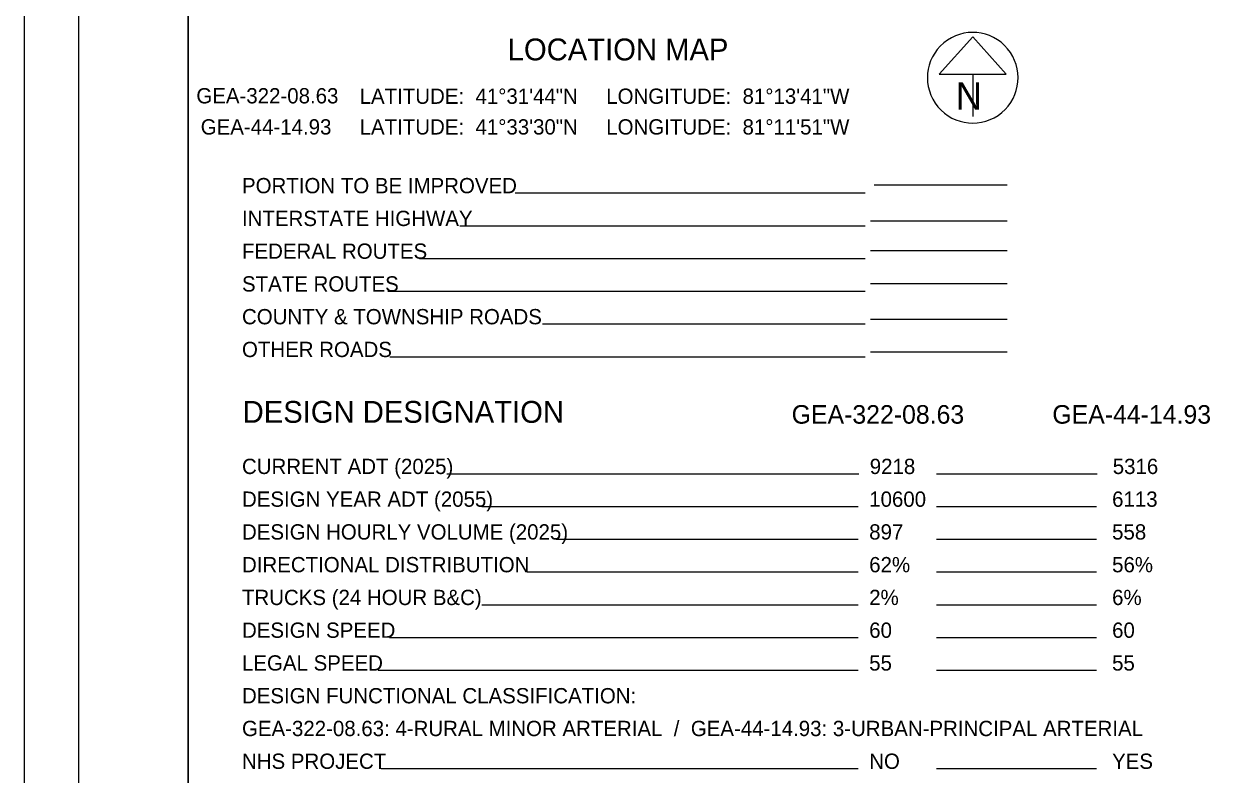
# Model space of a CAD drawing. Extents: x -6.1 to 38, y -7.7 to 22.
# Drawn here: x 0 to 11.09, y 7.05 to 13.93 of the extents above; entities that cross this region are included whole.
import ezdxf

# ---------------------------------------------------------------- set-up
doc = ezdxf.new("R2010")
doc.units = 0
for name, color, linetype in [('Default', 7, 'Continuous'), ('SH_Border', 7, 'Continuous'), ('SH_Cut_Line', 7, 'Continuous'), ('SH_Data', 7, 'Continuous'), ('SH_Text', 7, 'Continuous')]:
    doc.layers.add(name, color=color, linetype=linetype)

msp = doc.modelspace()

# ---------------------------------------------------------------- linework, layer by layer
at = {"layer": 'SH_Border'}
for points in [[(0.5, 21.5), (1.5, 21.5), (1.5, 0.5), (0.5, 0.5)], [(1.5, 21.5), (33.5, 21.5), (33.5, 0.5), (1.5, 0.5)]]:
    msp.add_lwpolyline(points, close=True, dxfattribs=at)
at = {"layer": 'SH_Cut_Line'}
msp.add_lwpolyline([(0, 0), (34, 0), (34, 22), (0, 22)], close=True, dxfattribs=at)
at = {"layer": 'SH_Data'}
for p, q in [((8.685, 13.809), (8.377, 13.468)), ((8.992, 13.468), (8.685, 13.809)), ((8.377, 13.468), (8.992, 13.468)), ((8.685, 13.468), (8.685, 13.081)), ((8.685, 13.435), (8.685, 13.435)), ((8.685, 13.435), (8.685, 13.435)), ((7.783, 12.455), (9, 12.455)), ((7.7, 12.377), (4.494, 12.377)), ((9, 12.121), (7.75, 12.121)), ((7.7, 12.077), (3.99, 12.077)), ((7.7, 11.777), (3.619, 11.777)), ((9, 11.849), (7.75, 11.849)), ((9, 11.549), (7.75, 11.549)), ((7.7, 11.477), (3.329, 11.477)), ((9, 11.222), (7.75, 11.222)), ((7.7, 11.177), (4.745, 11.177)), ((7.7, 10.877), (3.347, 10.877)), ((9, 10.922), (7.75, 10.922)), ((7.642, 9.806), (3.871, 9.806)), ((9.824, 9.806), (8.352, 9.806)), ((7.637, 9.506), (4.189, 9.506)), ((9.818, 9.506), (8.352, 9.506)), ((7.637, 9.206), (4.872, 9.206)), ((9.818, 9.206), (8.352, 9.206)), ((7.637, 8.906), (4.604, 8.906)), ((9.818, 8.906), (8.352, 8.906)), ((7.637, 8.606), (4.189, 8.606)), ((9.818, 8.606), (8.352, 8.606)), ((7.637, 8.306), (3.346, 8.306)), ((9.818, 8.306), (8.352, 8.306)), ((7.637, 8.006), (3.242, 8.006)), ((9.818, 8.006), (8.352, 8.006)), ((7.637, 7.106), (3.267, 7.106)), ((9.818, 7.106), (8.352, 7.106))]:
    msp.add_line(p, q, dxfattribs=at)
msp.add_arc((8.685, 13.435), 0.415, 129.7798, 129.7633, dxfattribs=at)

# ---------------------------------------------------------------- texts
at = {"layer": 'Default'}
for s, height, p in [('GEA-322-08.63', 0.14, (1.576, 13.2)), ('GEA-44-14.93', 0.14, (1.616, 12.915)), ('GEA-322-08.63', 0.17, (7.027, 10.267)), ('GEA-44-14.93', 0.17, (9.414, 10.267)), ('5316', 0.14, (9.967, 9.806)), ('6113', 0.14, (9.961, 9.506)), ('558', 0.14, (9.961, 9.206)), ('56%', 0.14, (9.961, 8.906)), ('6%', 0.14, (9.961, 8.606)), ('60', 0.14, (9.961, 8.306)), ('55', 0.14, (9.961, 8.006)), ('YES', 0.14, (9.961, 7.106))]:
    msp.add_text(s, height=height, dxfattribs=at).set_placement(p)
at = {"layer": 'SH_Data'}
for s, height, p in [('N', 0.25, (8.529, 13.144)), ('DESIGN DESIGNATION', 0.2, (2, 10.275))]:
    msp.add_text(s, height=height, dxfattribs=at).set_placement(p)
at = {"layer": 'SH_Text'}
for s, height, p in [('LOCATION MAP', 0.2, (4.427, 13.594)), ('LATITUDE:  41°31\'44"N     LONGITUDE:  81°13\'41"W', 0.14, (3.071, 13.196)), ('LATITUDE:  41°33\'30"N     LONGITUDE:  81°11\'51"W', 0.14, (3.071, 12.915)), ('PORTION TO BE IMPROVED', 0.14, (1.994, 12.377)), ('INTERSTATE HIGHWAY', 0.14, (1.994, 12.077)), ('FEDERAL ROUTES', 0.14, (1.994, 11.777)), ('STATE ROUTES', 0.14, (1.994, 11.477)), ('COUNTY & TOWNSHIP ROADS', 0.14, (1.994, 11.177)), ('OTHER ROADS', 0.14, (1.994, 10.877)), ('CURRENT ADT (2025)', 0.14, (1.994, 9.806)), ('9218', 0.14, (7.742, 9.806)), ('DESIGN YEAR ADT (2055)', 0.14, (1.994, 9.506)), ('10600', 0.14, (7.737, 9.506)), ('DESIGN HOURLY VOLUME (2025)', 0.14, (1.994, 9.206)), ('897', 0.14, (7.737, 9.206)), ('DIRECTIONAL DISTRIBUTION', 0.14, (1.994, 8.906)), ('62%', 0.14, (7.737, 8.906)), ('TRUCKS (24 HOUR B&C)', 0.14, (1.994, 8.606)), ('2%', 0.14, (7.737, 8.606)), ('DESIGN SPEED', 0.14, (1.994, 8.306)), ('60', 0.14, (7.737, 8.306)), ('LEGAL SPEED', 0.14, (1.994, 8.006)), ('55', 0.14, (7.737, 8.006)), ('DESIGN FUNCTIONAL CLASSIFICATION:', 0.14, (1.994, 7.706)), ('GEA-322-08.63: 4-RURAL MINOR ARTERIAL  /  GEA-44-14.93: 3-URBAN-PRINCIPAL ARTERIAL', 0.14, (1.994, 7.406)), ('NHS PROJECT', 0.14, (1.994, 7.106)), ('NO', 0.14, (7.737, 7.106))]:
    msp.add_text(s, height=height, dxfattribs=at).set_placement(p)

doc.saveas('drawing.dxf')
